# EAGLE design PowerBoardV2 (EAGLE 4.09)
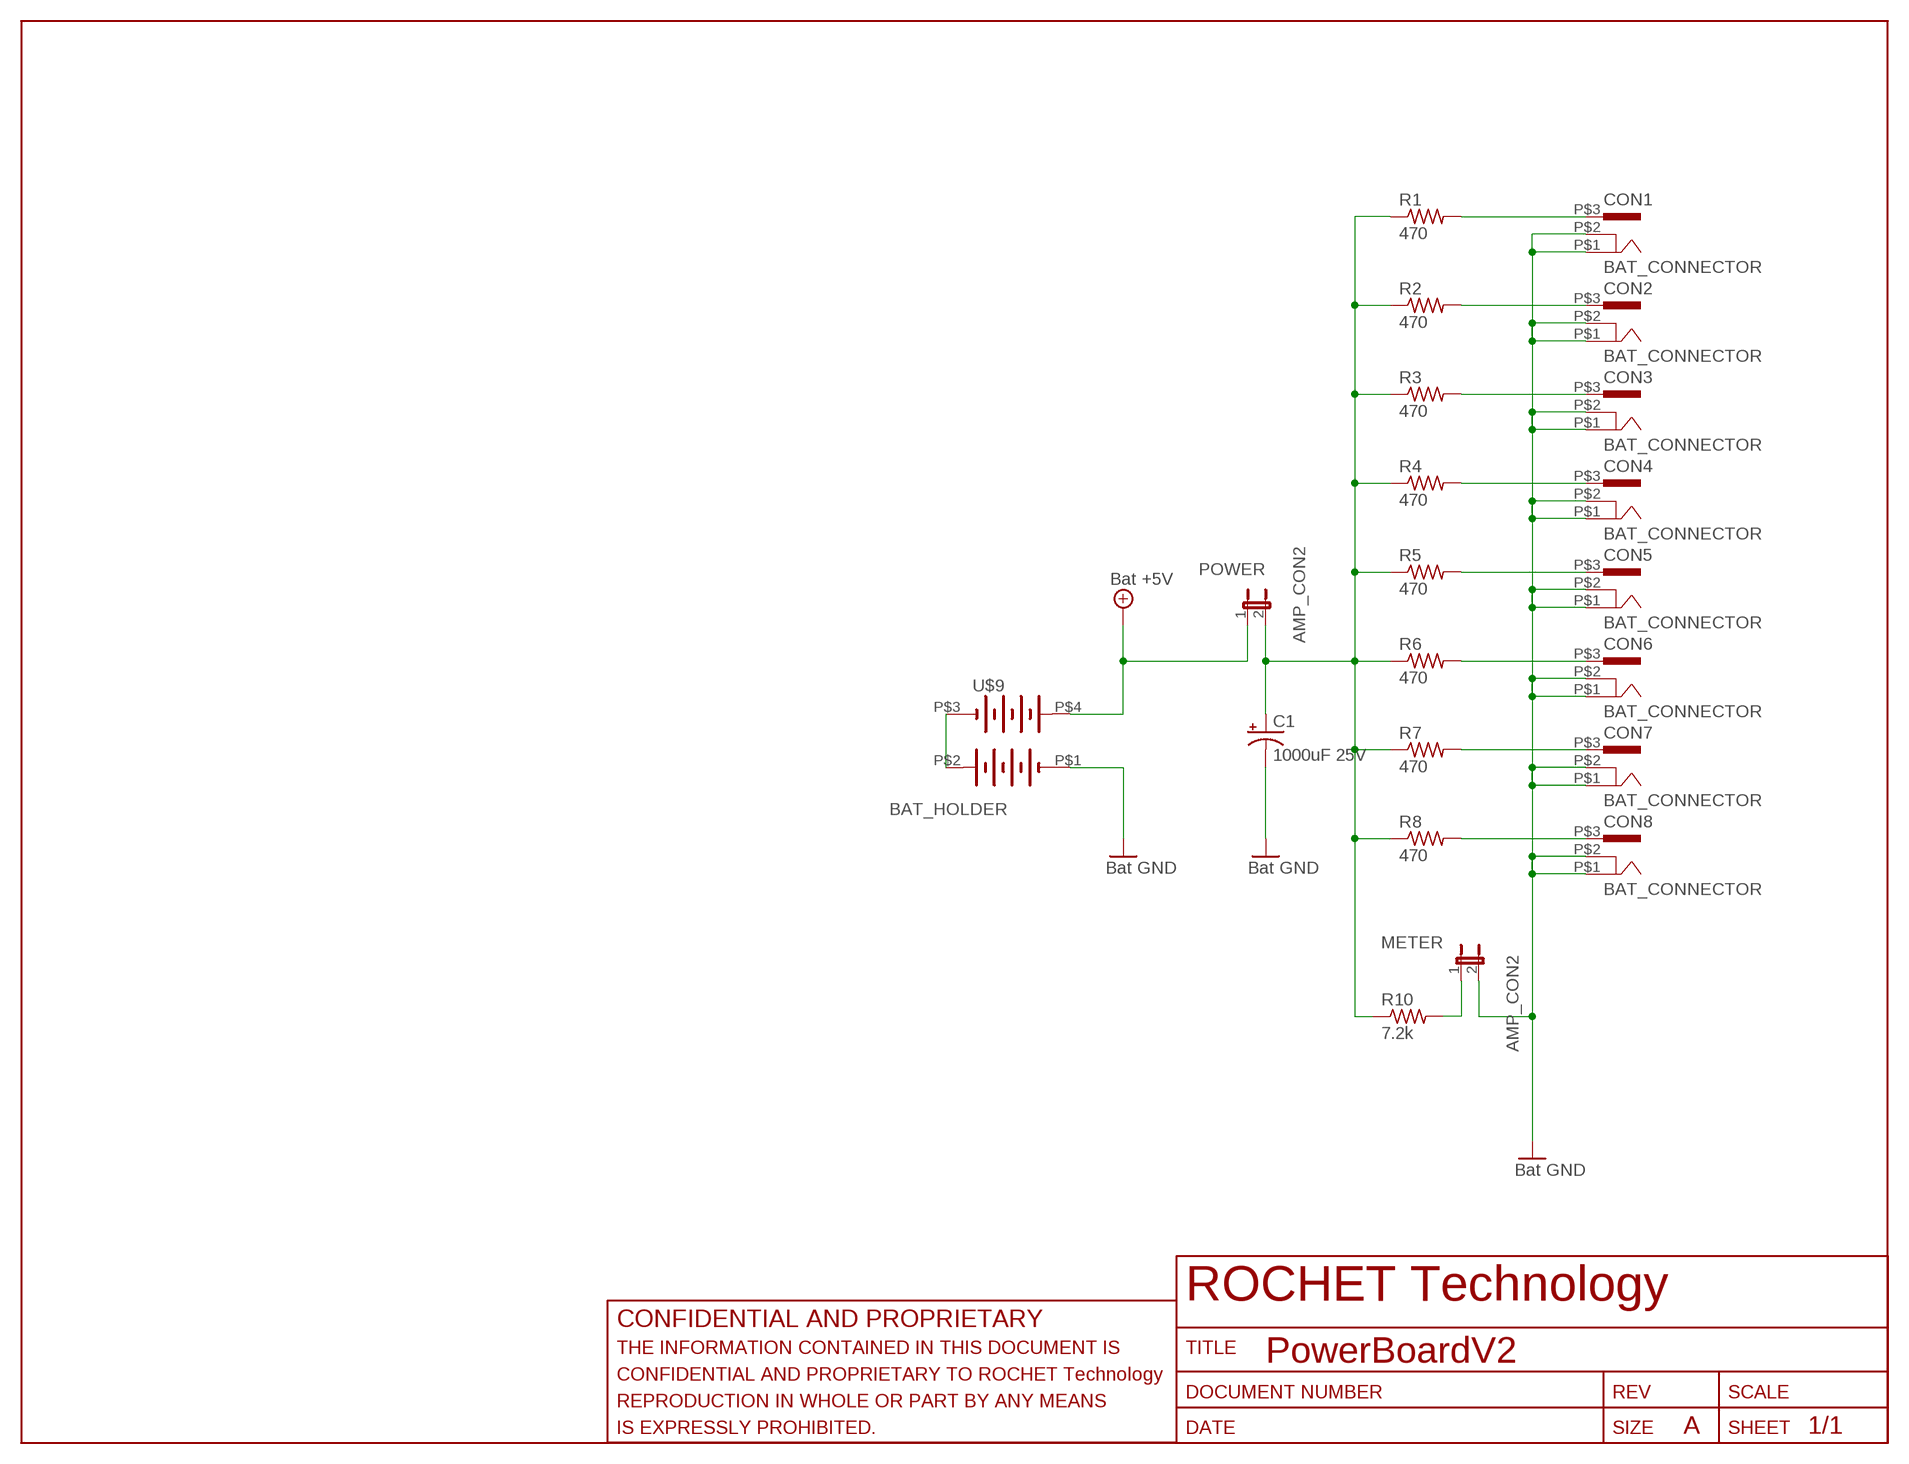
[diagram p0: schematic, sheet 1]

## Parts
C1  1000uF 25V  CPOL-USE5-13  [E5-13]
CON1  BAT_CONNECTOR  [PJ-022]
CON2  BAT_CONNECTOR  [PJ-022]
CON3  BAT_CONNECTOR  [PJ-022]
CON4  BAT_CONNECTOR  [PJ-022]
CON5  BAT_CONNECTOR  [PJ-022]
CON6  BAT_CONNECTOR  [PJ-022]
CON7  BAT_CONNECTOR  [PJ-022]
CON8  BAT_CONNECTOR  [PJ-022]
METER  AMP_CON2  [AMP_CON]
POWER  AMP_CON2  [AMP_CON]
R1  470  R-US_0207/10  [0207/10]
R2  470  R-US_0207/10  [0207/10]
R3  470  R-US_0207/10  [0207/10]
R4  470  R-US_0207/10  [0207/10]
R5  470  R-US_0207/10  [0207/10]
R6  470  R-US_0207/10  [0207/10]
R7  470  R-US_0207/10  [0207/10]
R8  470  R-US_0207/10  [0207/10]
R10  7.2k  R-US_0207/10  [0207/10]
U$9  BAT_HOLDER  [BATTERY_HOLDER]

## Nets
+5V: POWER.1 U$9.P$4(+) ; supply symbol labelled Bat +5V
GND: C1.- CON1.P$1 CON1.P$2 CON2.P$1 CON2.P$2 CON3.P$1 CON3.P$2 CON4.P$1 CON4.P$2 CON5.P$1 CON5.P$2 CON6.P$1 CON6.P$2 CON7.P$1 CON7.P$2 CON8.P$1 CON8.P$2 METER.2 U$9.P$1(-1) ; supply symbol labelled Bat GND
N$1: CON1.P$3 R1.2
N$2: CON2.P$3 R2.2
N$3: CON3.P$3 R3.2
N$4: CON4.P$3 R4.2
N$5: CON5.P$3 R5.2
N$6: CON6.P$3 R6.2
N$7: CON7.P$3 R7.2
N$8: CON8.P$3 R8.2
N$9: METER.1 R10.2
N$10: C1.+ POWER.2 R1.1 R2.1 R3.1 R4.1 R5.1 R6.1 R7.1 R8.1 R10.1
N$14: U$9.P$2(+1) U$9.P$3(-)

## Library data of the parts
C1 = rcl:CPOL-US: POLARIZED CAPACITOR, American symbol
CON1-CON8 = microboard:BAT_CONNECTOR
METER POWER = microboard:AMP_CON2
R1-R8 R10 = rcl:R-US_: RESISTOR, American symbol
U$9 = microboard:BAT_HOLDER

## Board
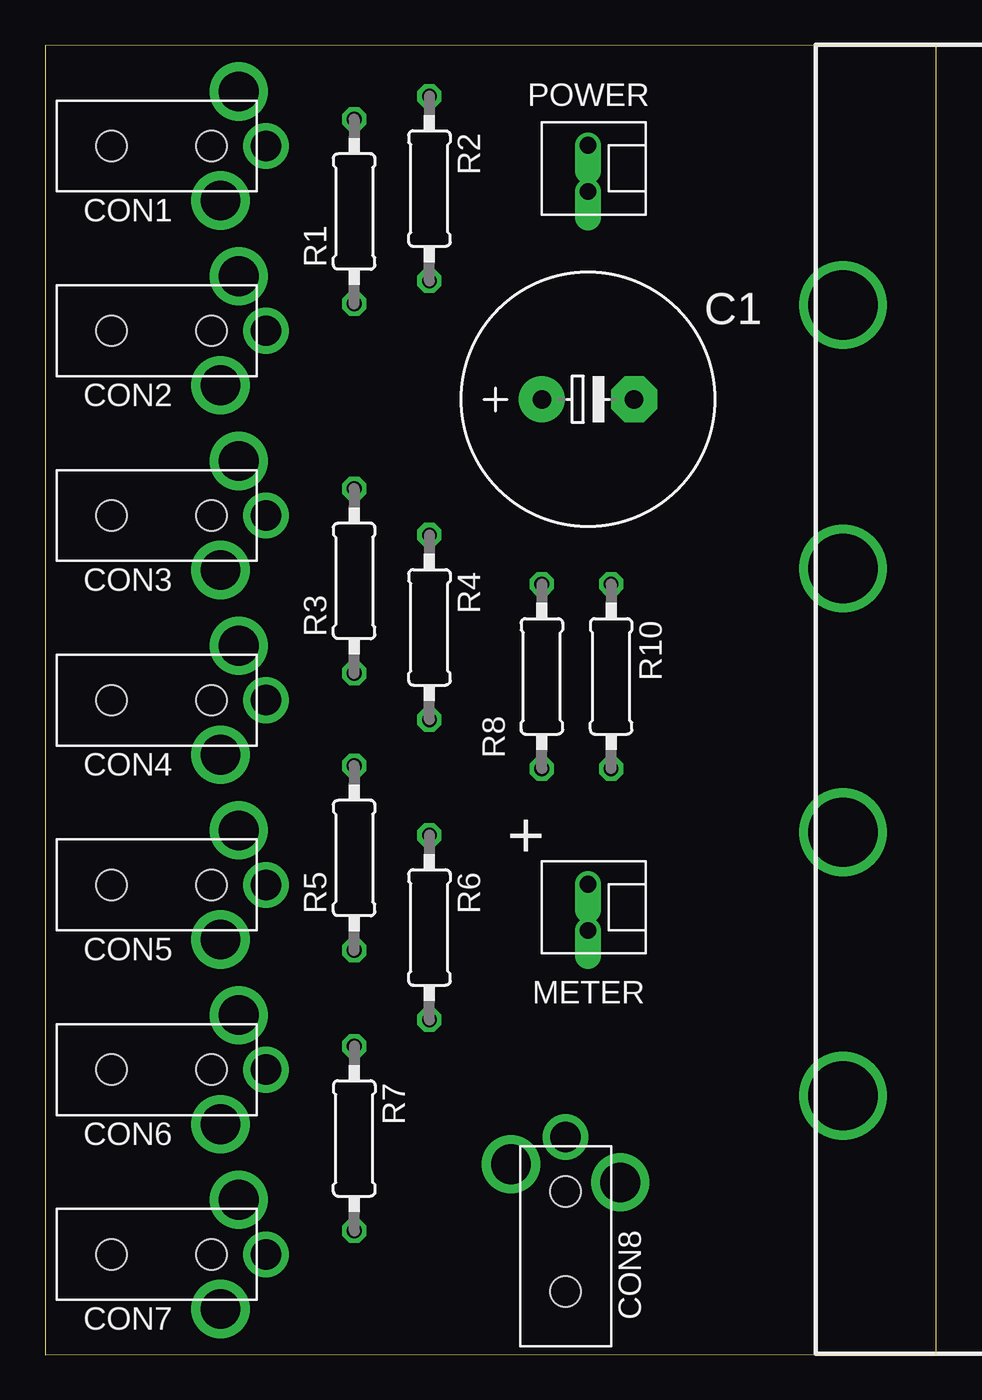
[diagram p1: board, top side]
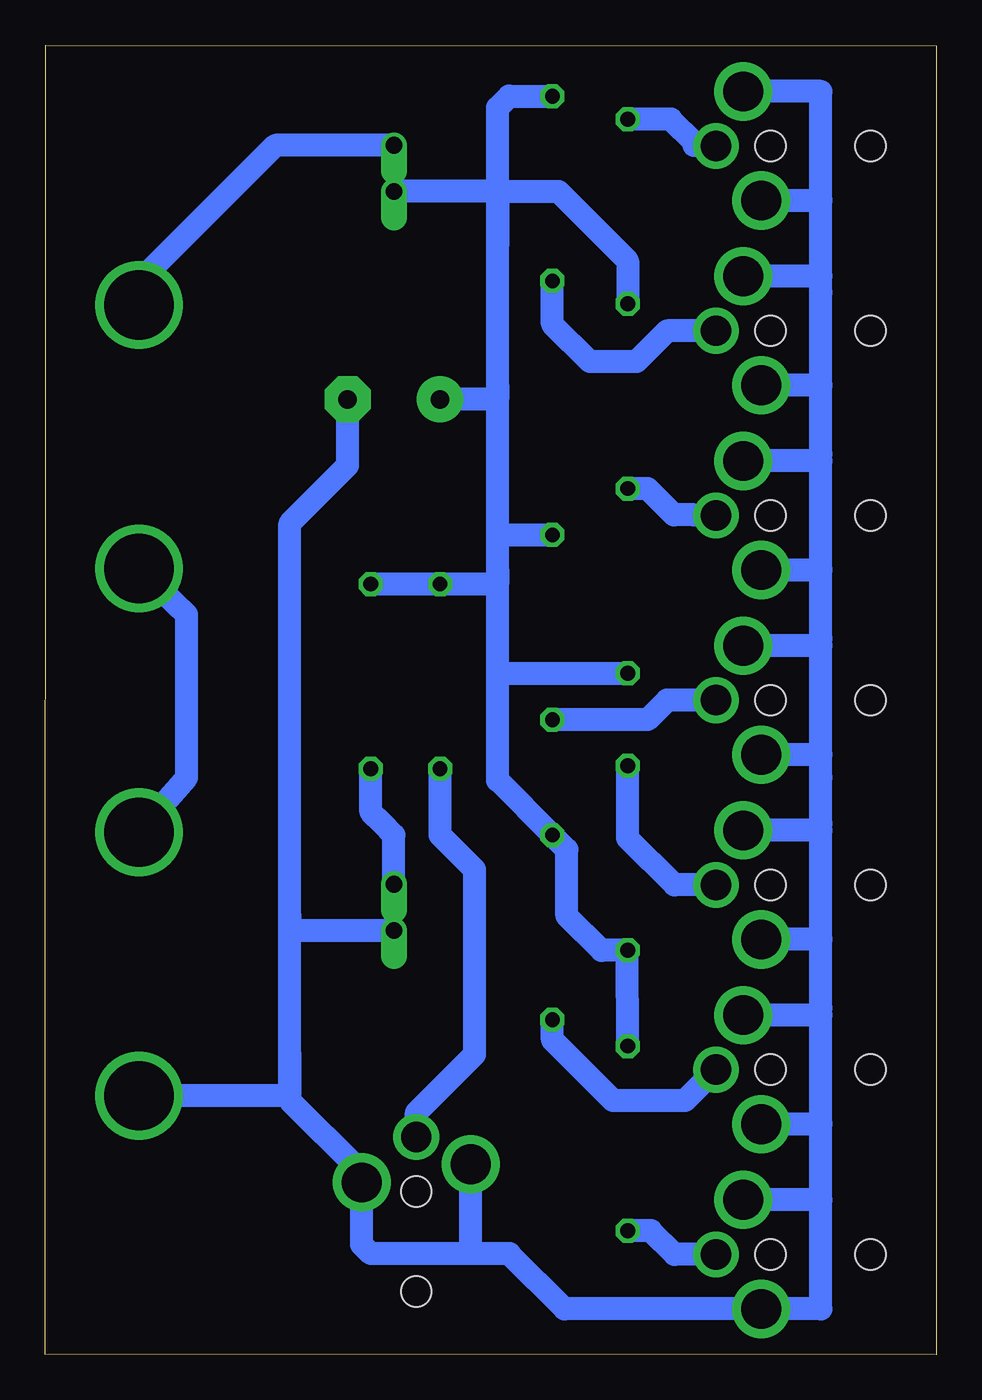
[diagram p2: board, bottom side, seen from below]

Size 49 x 72 mm. Coordinates in mm from the lower left corner, seen from the top.
Outline: 0,0 49.01,0.03 48.99,72 0,72 0,0
Copper layers used: Bottom

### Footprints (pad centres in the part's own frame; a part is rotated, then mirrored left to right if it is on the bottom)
E5-13 = drill 1.016 pad 2.54 round: + -2.54,0 | drill 1.016 pad 2.54 octagon: - 2.54,0
PJ-022 = drill 2.184 round: P$1 3.92,-3.04; P$2 4.92,2.96 | drill 1.676 round: P$3 6.42,-0.04 | hole 1.676: -2.08,-0.04; 3.42,-0.04
AMP_CON = drill 0.914 offset: 1 -1.27,0; 2 1.27,0
0207/10 = drill 0.813 octagon: 1 -5.08,0; 2 5.08,0
BATTERY_HOLDER = drill 3.81 round: P$1 -21.8,-1.5; P$2 -7.3,-1.5; P$3 7.2,-1.5; P$4 21.7,-1.5

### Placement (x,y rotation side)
C1  29.84,52.54 0 top
CON1  5.71,66.51 0 top
CON2  5.71,56.35 0 top
CON3  5.71,46.19 0 top
CON4  5.71,36.03 0 top
CON5  5.71,25.87 0 top
CON6  5.71,15.71 0 top
CON7  5.71,5.55 0 top
CON8  28.57,5.55 90 top
METER  29.84,24.6 270 top
POWER  29.84,65.24 270 top
R1  16.98,62.87 90 top
R2  21.12,64.13 270 top
R3  16.98,42.55 90 top
R4  21.12,40 270 top
R5  16.98,27.31 90 top
R6  21.12,23.49 270 top
R7  16.98,11.89 270 top
R8  27.3,37.3 270 top
R10  31.11,37.3 270 top
U$9  42.36,36.03 90 top

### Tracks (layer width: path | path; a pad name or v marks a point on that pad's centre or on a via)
+5V
  Bottom 1.27: POWER.1 36.36,66.51 43.86,59.01 U$9.P$4
GND
  Bottom 0.254: 6.35,53.31 | 6.35,53.31 | 6.35,53.34 6.35,53.31 | 6.35,49.15 6.35,49.53 | 6.34,43.15 6.34,43.13 | 6.35,43.15 6.34,43.15 | 6.35,43.18 6.34,43.18 6.34,43.15 | 6.35,38.99 6.36,38.99 6.36,39.37 6.35,39.37 | 6.35,28.83 6.35,28.82 | 6.35,28.83 | 6.35,29.21 6.35,28.83 | 6.35,22.83 6.35,22.82 | 6.35,22.83 | 6.35,22.86 6.35,22.83 | 6.36,18.67 6.36,18.64 | 6.35,18.67 6.36,18.67 | 6.35,19.05 6.36,19.05 6.36,18.67 | 6.35,12.67 6.35,12.61 | 6.35,12.67 | 6.35,12.7 6.35,12.67 | 6.34,63.47 6.34,63.46 | 6.35,63.47 6.34,63.47 | 6.35,63.5 6.34,63.5 6.34,63.47
  Bottom 1.27: 31.61,9.86 CON8.P$1 | 31.61,9.86 31.61,6.05 31.11,5.55 24.76,5.55 | 24.76,5.55 23.49,5.55 20.45,2.51 CON7.P$1 6.35,2.51 6.35,8.51 | CON8.P$2 25.61,5.55 24.76,5.55 | C1.- 32.38,48.9 35.56,45.72 35.56,24.13 | 35.56,16.51 35.56,24.13 | 35.56,16.51 35.56,13.97 31.75,10.16 31.75,9.86 | METER.2 35.56,23.33 35.56,24.13 | 35.56,16.51 35.56,15.5 | 31.75,9.86 31.75,8.89 | 31.61,9.86 31.75,9.86 | 6.35,8.51 CON7.P$2 | CON6.P$1 6.35,12.67 6.35,8.51 | CON6.P$2 6.35,18.67 6.35,12.7 | CON5.P$1 6.35,22.83 6.35,19.05 | CON5.P$2 6.35,28.83 6.35,22.86 | CON4.P$1 6.35,32.99 6.35,31.75 | 6.35,29.21 6.35,31.75 | CON4.P$2 6.35,38.99 6.35,31.75 | CON3.P$1 6.35,43.15 6.35,39.37 | CON3.P$2 6.35,49.15 6.35,43.18 | CON2.P$1 6.35,53.31 6.35,49.53 | CON2.P$2 6.35,59.31 6.35,58.42 | 6.35,53.34 6.35,58.42 | CON1.P$1 6.35,63.47 6.35,58.42 | CON1.P$2 6.35,69.47 6.35,63.5 | U$9.P$1 35.56,14.23 35.56,16.51
N$1
  Bottom 1.27: CON1.P$3 13.33,66.51 13.33,66.67 14.61,67.95 R1.2
N$2
  Bottom 1.27: CON2.P$3 14.81,56.31 16.51,54.61 19.05,54.61 21.12,56.68 R2.2
N$3
  Bottom 1.27: CON3.P$3 13.33,46.19 14.44,46.19 15.88,47.63 R3.2
N$4
  Bottom 1.27: CON4.P$3 14.81,35.99 15.88,34.92 R4.2
N$5
  Bottom 1.27: CON5.P$3 14.4,25.83 16.98,28.41 R5.2
N$6
  Bottom 1.27: CON6.P$3 13.83,13.97 17.78,13.97 21.12,17.31 R6.2
N$7
  Bottom 1.27: CON7.P$3 14.4,5.51 15.71,6.82 R7.2
N$8
  Bottom 1.27: R8.2 27.3,28.57 25.4,26.67 25.4,16.51 28.61,13.3 CON8.P$3
N$9
  Bottom 1.27: METER.1 29.84,28.57 30.48,29.21 31.11,29.84 R10.2
N$10
  Bottom 0.254: 24.13,63.97 24.16,63.97 24.17,63.97
  Bottom 1.27: R7.1 17,22.25 R5.1 18.42,22.23 20.32,24.13 20.32,27.77 R6.1 24.13,31.58 24.13,36.83 | R10.1 R8.1 24.13,42.38 24.13,43.18 | 24.13,43.18 24.13,53.34 | 24.13,53.34 24.13,63.5 | R3.1 24.13,37.47 24.13,36.83 | 24.13,36.83 24.13,43.18 | R4.1 24.13,45.08 24.13,43.18 | C1.+ 24.13,52.54 24.13,53.34 | 24.13,63.5 24.13,60.96 | R2.1 23.5,69.21 24.13,68.58 24.13,63.97 | 24.13,63.5 24.13,63.97 | 24.13,63.97 20.79,63.97 16.98,60.16 R1.1 | 24.13,63.97 POWER.2
N$14
  Bottom 1.27: U$9.P$2 41.24,31.73 41.24,40.69 U$9.P$3

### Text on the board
tNames: +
